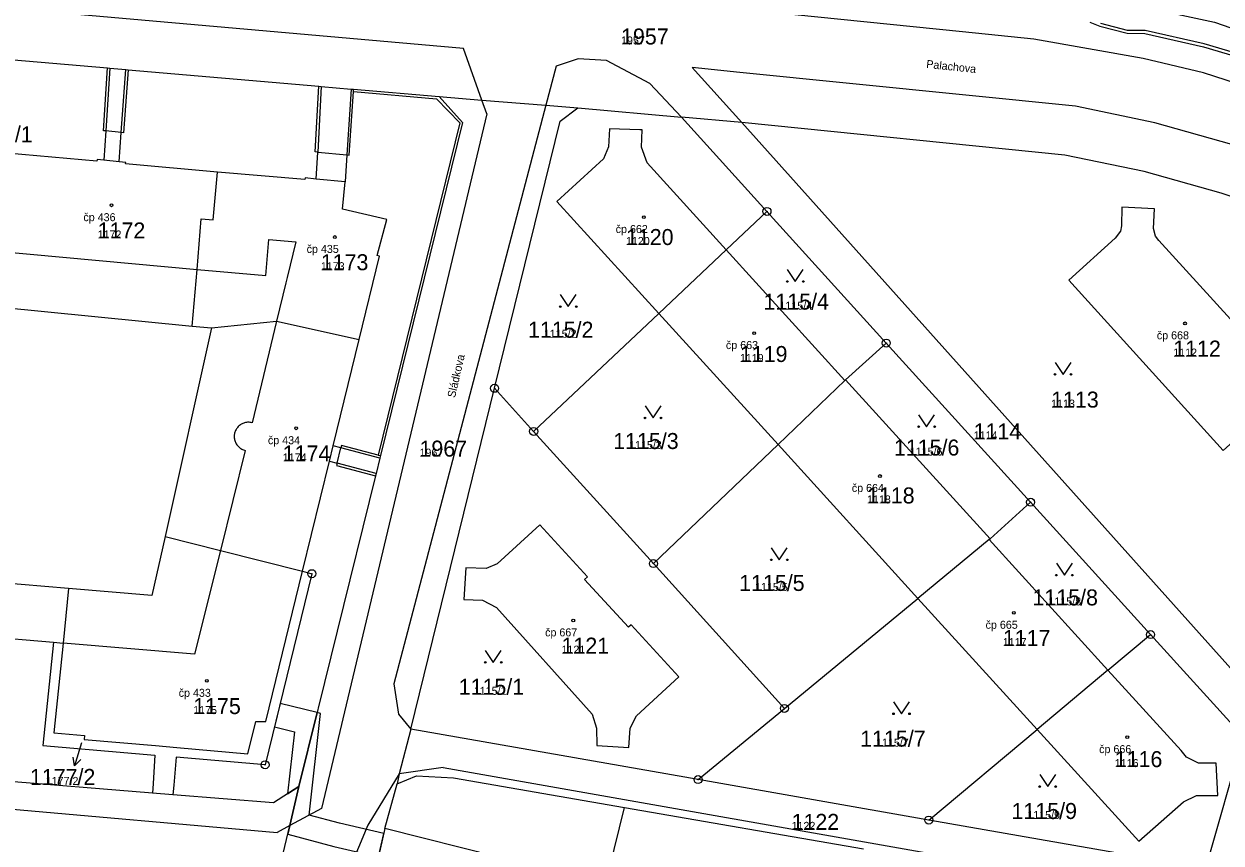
# Model space of a CAD drawing. Extents: x -763628 to -761565, y -976033 to -973833.
# Drawn here: x -762144.5 to -761994.9, y -975118.1 to -975015.7 of the extents above; entities that cross this region are included whole.
import ezdxf

# ---------------------------------------------------------------- set-up
doc = ezdxf.new("R2010")
doc.units = 0
for name, color, linetype in [('KN_cisla parcel 1000', 7, 'Continuous'), ('KN_cisla parcel 500', 7, 'Continuous'), ('KN_cisla parcel znacky', 7, 'Continuous'), ('KN_cisla popisna 500', 7, 'Continuous'), ('KN_hranice parcel', 7, 'Continuous'), ('KN_popisy', 7, 'Continuous'), ('KN_vecna bremena', 7, 'Continuous'), ('KN_vnitrni kresba parcel', 7, 'Continuous'), ('KN_znacky bodu BP', 7, 'Continuous'), ('KN_znacky budov', 7, 'Continuous'), ('KN_znacky kultur', 7, 'Continuous')]:
    doc.layers.add(name, color=color, linetype=linetype)

msp = doc.modelspace()

# ---------------------------------------------------------------- linework, layer by layer
at = {"layer": 'KN_cisla parcel znacky'}
for p, q in [((-762137.32, -975105.63), (-762138.2, -975108.5)), ((-762138.2, -975108.5), (-762138.38, -975107.4)), ((-762138.2, -975108.5), (-762137.43, -975107.69))]:
    msp.add_line(p, q, dxfattribs=at)
at = {"layer": 'KN_hranice parcel'}
for p, q in [((-762075.32, -975026.21), (-762062.36, -975027.36)), ((-762054.8, -975028.04), (-762062.36, -975027.36)), ((-762062.36, -975027.36), (-762051.67, -975039.16)), ((-762054.8, -975028.04), (-761990.72, -975099.69)), ((-762056.78, -975043.98), (-762051.67, -975039.16)), ((-762051.67, -975039.16), (-762036.76, -975055.62)), ((-762056.78, -975043.98), (-762065.19, -975051.92)), ((-762041.95, -975060.32), (-762056.78, -975043.98)), ((-762148.53, -975051.01), (-762123.49, -975053.49)), ((-762080.83, -975066.67), (-762065.19, -975051.92)), ((-762065.19, -975051.92), (-762050.29, -975068.31)), ((-762121.08, -975053.73), (-762126.89, -975079.8)), ((-762123.49, -975053.49), (-762121.08, -975053.73)), ((-762041.84, -975060.22), (-762036.76, -975055.62)), ((-762036.76, -975055.62), (-762018.73, -975075.52)), ((-762041.84, -975060.22), (-762041.95, -975060.32)), ((-762023.79, -975080.09), (-762041.84, -975060.22)), ((-762096.2, -975103.92), (-762085.72, -975061.28)), ((-762080.83, -975066.67), (-762085.72, -975061.28)), ((-762041.95, -975060.32), (-762050.29, -975068.31)), ((-762065.87, -975083.2), (-762080.83, -975066.67)), ((-762065.87, -975083.2), (-762050.29, -975068.31)), ((-762050.29, -975068.31), (-762032.81, -975087.55)), ((-762023.79, -975080.09), (-762018.73, -975075.52)), ((-762018.73, -975075.52), (-762003.73, -975092.08)), ((-762023.9, -975080.19), (-762032.81, -975087.55)), ((-762023.9, -975080.19), (-762023.79, -975080.09)), ((-762009.07, -975096.52), (-762023.9, -975080.19)), ((-762049.5, -975101.31), (-762065.87, -975083.2)), ((-762049.5, -975101.31), (-762032.81, -975087.55)), ((-762032.81, -975087.55), (-762017.92, -975103.94)), ((-762140.85, -975093.03), (-762139.65, -975093.13)), ((-762009.07, -975096.52), (-762003.73, -975092.08)), ((-762003.73, -975092.08), (-761992.18, -975104.83)), ((-762009.07, -975096.52), (-762017.92, -975103.94)), ((-762060.28, -975110.21), (-762049.5, -975101.31)), ((-762060.28, -975110.21), (-762096.2, -975103.92)), ((-762031.45, -975115.27), (-762017.92, -975103.94)), ((-761992.18, -975104.83), (-761996.86, -975121.33)), ((-762128.45, -975111.89), (-762150.74, -975110.1)), ((-762099.41, -975116.32), (-762097.9, -975110.76)), ((-762090.86, -975110.01), (-762069.47, -975113.71)), ((-762031.45, -975115.27), (-762060.28, -975110.21)), ((-762125.91, -975112.1), (-762128.45, -975111.89)), ((-762077.74, -975147.37), (-762069.47, -975113.71)), ((-762069.47, -975113.71), (-762039.6, -975118.87)), ((-761996.86, -975121.33), (-762031.45, -975115.27)), ((-762099.41, -975116.32), (-762101.69, -975126.28))]:
    msp.add_line(p, q, dxfattribs=at)
for points in [[(-762003.31, -975013.86), (-761995.75, -975015.5), (-761988.77, -975017.9), (-761988.34, -975018.04), (-761985.18, -975019.03)], [(-762197.02, -975015.78), (-762187.5, -975016.6), (-762187.21, -975016.63), (-762185.26, -975016.8), (-762184.97, -975016.82), (-762160.6, -975018.93), (-762160.3, -975018.95), (-762158.34, -975019.12), (-762158.04, -975019.15), (-762134.08, -975021.22), (-762133.78, -975021.24), (-762131.8, -975021.42), (-762131.5, -975021.44), (-762107.67, -975023.5), (-762107.37, -975023.53), (-762103.63, -975023.85), (-762103.34, -975023.88), (-762092.64, -975024.8)], [(-762092.64, -975024.8), (-762089.73, -975028.02), (-762099.99, -975069.7), (-762100.06, -975070), (-762100.53, -975071.92), (-762100.6, -975072.21), (-762110.16, -975111.06)], [(-762092.64, -975024.8), (-762087.3, -975025.23), (-762079.29, -975025.89), (-762075.32, -975026.21)], [(-762085.72, -975061.28), (-762077.5, -975027.86), (-762075.32, -975026.21)], [(-762056.78, -975043.98), (-762066.66, -975033.1), (-762067.35, -975031.14), (-762067.28, -975028.97), (-762067.58, -975028.96), (-762071.37, -975028.84), (-762071.49, -975031.07), (-762072.09, -975032.58), (-762077.93, -975037.9), (-762065.19, -975051.92)], [(-761977.51, -975044.15), (-761979.7, -975042.42), (-761987.36, -975039.43), (-761994.91, -975036.88), (-762004.52, -975034.15), (-762014.44, -975032.12), (-762054.8, -975028.04)], [(-762120.35, -975034.25), (-762131.83, -975033.22), (-762131.81, -975033.04), (-762132.64, -975032.95), (-762134.55, -975032.75), (-762135.4, -975032.66), (-762135.42, -975032.88), (-762146.69, -975031.88)], [(-762123.49, -975053.49), (-762122.9, -975046.4), (-762122.37, -975040.1), (-762120.87, -975040.23), (-762120.35, -975034.25)], [(-762102.64, -975055.16), (-762100.1, -975044.77), (-762100.39, -975044.69), (-762099.19, -975040.18), (-762104.7, -975038.89), (-762104.4, -975035.47), (-762108.01, -975035.11), (-762109.39, -975034.97), (-762109.41, -975035.16), (-762120.35, -975034.25)], [(-762007.38, -975040.97), (-762007.5, -975041.64), (-762008.16, -975042.49), (-762013.95, -975047.77), (-761994.66, -975069.04), (-761988.76, -975063.7), (-761987.08, -975063.17), (-761984.81, -975063.25), (-761984.64, -975059.18), (-761986.84, -975059.01), (-761988.64, -975058.26), (-762002.72, -975042.8), (-762003.11, -975042.25), (-762003.38, -975041.31), (-762003.26, -975038.84), (-762007.33, -975038.64), (-762007.38, -975040.97)], [(-762121.08, -975053.73), (-762112.96, -975052.9), (-762102.64, -975055.16)], [(-762109.72, -975084.16), (-762106.36, -975070.39), (-762105.89, -975068.48), (-762102.64, -975055.16)], [(-762068.99, -975091.16), (-762074.46, -975085.19), (-762074.1, -975084.86), (-762080.04, -975078.37), (-762085.39, -975083.22), (-762086.78, -975083.81), (-762089.32, -975083.74), (-762089.56, -975087.7), (-762087.22, -975087.78), (-762085.46, -975088.7), (-762073.51, -975102.02), (-762072.96, -975103.78), (-762072.93, -975105.96), (-762068.93, -975106.19), (-762068.78, -975103.76), (-762067.99, -975102.24), (-762062.67, -975097.37), (-762068.64, -975090.84), (-762068.99, -975091.16)], [(-762126.89, -975079.8), (-762128.53, -975087.18), (-762138.95, -975086.31), (-762139.65, -975093.13)], [(-762126.89, -975079.8), (-762119.98, -975081.55), (-762109.72, -975084.16)], [(-762139.65, -975093.13), (-762140.8, -975104.35), (-762136.95, -975104.7), (-762136.99, -975105.18), (-762128.08, -975105.96), (-762125.42, -975106.2), (-762116.57, -975106.97), (-762115.57, -975102.93), (-762114.3, -975102.93), (-762109.72, -975084.16)], [(-762109.72, -975084.16), (-762108.56, -975084.46), (-762114.39, -975108.36), (-762125.52, -975107.4), (-762125.81, -975110.9), (-762125.91, -975112.1)], [(-762150.74, -975110.1), (-762154.66, -975108.46), (-762156.03, -975105.41), (-762155.42, -975097.52), (-762153.33, -975094.1), (-762149.67, -975092.29), (-762140.85, -975093.03)], [(-762140.85, -975093.03), (-762142.17, -975105.93), (-762128.16, -975107.16), (-762128.38, -975110.69), (-762128.45, -975111.89)], [(-762017.92, -975103.94), (-762005.2, -975117.93), (-761999.6, -975113.01), (-761997.99, -975112.21), (-761995.31, -975112.22), (-761995.52, -975108.16), (-761997.73, -975108.16), (-761999.24, -975107.39), (-761999.93, -975106.59), (-762009.07, -975096.52)], [(-762096.2, -975103.92), (-762097.63, -975109.51), (-762097.9, -975110.76)], [(-762110.16, -975111.06), (-762113.34, -975113.11), (-762125.91, -975112.1)], [(-762113.48, -975125.21), (-762112.7, -975121.9), (-762111.31, -975115.95), (-762110.16, -975111.06)], [(-762097.9, -975110.76), (-762095.49, -975109.76), (-762090.86, -975110.01)], [(-762087.88, -975144.88), (-762084.3, -975130.34), (-762087.6, -975129.52), (-762085.23, -975119.93), (-762099.41, -975116.32)]]:
    msp.add_lwpolyline(points, dxfattribs=at)
at = {"layer": 'KN_vecna bremena'}
for points in [[(-762011.34, -975015.47), (-762010.07, -975016.01), (-762006.64, -975016.86), (-762004.44, -975016.89), (-761997.13, -975018.56), (-761989.39, -975020.85)], [(-761989.29, -975020.51), (-761997.05, -975018.22), (-762004.4, -975016.55), (-762006.6, -975016.52), (-762009.95, -975015.67)]]:
    msp.add_lwpolyline(points, dxfattribs=at)
for points in [[(-762112.52, -975100.71), (-762113.23, -975103.62), (-762110.73, -975104.23), (-762111.6, -975111.99), (-762110.16, -975111.06), (-762107.89, -975101.84)], [(-762107.89, -975101.84), (-762110.16, -975111.06), (-762111.31, -975115.95), (-762111.56, -975117.03), (-762105.82, -975118.56), (-762100.23, -975119.89), (-762099.56, -975116.96), (-762105.09, -975115.65), (-762108.87, -975114.64), (-762107.45, -975101.95)]]:
    msp.add_lwpolyline(points, close=True, dxfattribs=at)
at = {"layer": 'KN_vnitrni kresba parcel'}
for p, q in [((-762089.61, -975018.78), (-762197.77, -975009.24)), ((-762027.23, -975016.7), (-762070.01, -975012.34)), ((-762018.31, -975017.63), (-762027.23, -975016.7)), ((-762004.64, -975020.02), (-762018.31, -975017.63)), ((-762087.3, -975025.23), (-762089.61, -975018.78)), ((-762134.6, -975029.07), (-762134.08, -975021.22)), ((-762133.78, -975021.24), (-762134.3, -975029.09)), ((-762078, -975021), (-762079.29, -975025.89)), ((-762075.26, -975020.08), (-762078, -975021)), ((-762071.72, -975020.3), (-762075.26, -975020.08)), ((-762066.3, -975023.14), (-762071.72, -975020.3)), ((-762061.03, -975021.17), (-762054.8, -975028.04)), ((-762055.06, -975021.77), (-762061.03, -975021.17)), ((-761997.12, -975021.83), (-762004.64, -975020.02)), ((-762132.37, -975029.29), (-762131.8, -975021.42)), ((-762131.5, -975021.44), (-762132.07, -975029.31)), ((-762013.12, -975026), (-762055.06, -975021.77)), ((-761982.88, -975026.4), (-761997.12, -975021.83)), ((-762108.12, -975031.71), (-762107.67, -975023.5)), ((-762107.37, -975023.53), (-762107.82, -975031.73)), ((-762103.63, -975023.85), (-762104.18, -975032.09)), ((-762103.88, -975032.11), (-762103.35, -975024.17)), ((-762103.35, -975024.17), (-762103.34, -975023.88)), ((-762103.35, -975024.17), (-762092.97, -975025.07)), ((-762062.36, -975027.36), (-762066.3, -975023.14)), ((-762092.97, -975025.07), (-762090.06, -975028.09)), ((-762086.69, -975026.94), (-762087.3, -975025.23)), ((-762086.69, -975026.94), (-762107.35, -975113.81)), ((-762079.29, -975025.89), (-762098.32, -975098.23)), ((-762003.2, -975028.07), (-762013.12, -975026)), ((-762090.06, -975028.09), (-762100.28, -975069.62)), ((-761993.59, -975030.77), (-762003.2, -975028.07)), ((-762134.3, -975029.09), (-762134.6, -975029.07)), ((-762134.3, -975029.09), (-762134.55, -975032.75)), ((-762132.37, -975029.29), (-762134.3, -975029.09)), ((-762132.64, -975032.95), (-762132.37, -975029.29)), ((-762132.07, -975029.31), (-762132.37, -975029.29)), ((-762107.82, -975031.73), (-762108.12, -975031.71)), ((-762108.01, -975035.11), (-762107.82, -975031.73)), ((-762107.82, -975031.73), (-762104.18, -975032.09)), ((-762104.18, -975032.09), (-762104.4, -975035.47)), ((-762104.18, -975032.09), (-762103.88, -975032.11)), ((-762114.32, -975047.18), (-762113.91, -975042.68)), ((-762113.91, -975042.68), (-762110.57, -975042.96)), ((-762110.57, -975042.96), (-762111.65, -975047.42)), ((-762147.87, -975044.13), (-762122.9, -975046.4)), ((-762122.9, -975046.4), (-762114.32, -975047.18)), ((-762111.81, -975048.1), (-762112.96, -975052.9)), ((-762111.65, -975047.42), (-762111.81, -975048.1)), ((-762112.96, -975052.9), (-762116.02, -975065.59)), ((-762116.87, -975069.04), (-762119.98, -975081.55)), ((-762104.92, -975068.73), (-762105.89, -975068.48)), ((-762105.39, -975070.63), (-762104.92, -975068.73)), ((-762104.85, -975068.44), (-762104.92, -975068.73)), ((-762100.06, -975070), (-762104.92, -975068.73)), ((-762100.28, -975069.62), (-762104.85, -975068.44)), ((-762106.36, -975070.39), (-762105.39, -975070.63)), ((-762105.39, -975070.63), (-762105.46, -975070.92)), ((-762100.53, -975071.92), (-762105.39, -975070.63)), ((-762100.28, -975069.62), (-762099.99, -975069.7)), ((-762105.46, -975070.92), (-762100.6, -975072.21)), ((-762119.98, -975081.55), (-762123.22, -975094.54)), ((-762138.95, -975086.31), (-762174.14, -975083.36)), ((-762123.22, -975094.54), (-762139.65, -975093.13)), ((-762098.32, -975098.23), (-762097.73, -975102.02)), ((-762097.73, -975102.02), (-762096.2, -975103.92)), ((-762206.5, -975108.64), (-762112.89, -975116.81)), ((-762097.63, -975109.51), (-762101.57, -975115.89)), ((-762092.15, -975108.68), (-762097.63, -975109.51)), ((-762092.15, -975108.68), (-762005.33, -975124)), ((-762107.35, -975113.81), (-762111.31, -975115.95)), ((-762111.31, -975115.95), (-762112.89, -975116.81)), ((-762101.57, -975115.89), (-762104.35, -975122.6))]:
    msp.add_line(p, q, dxfattribs=at)
msp.add_lwpolyline([(-762116.02, -975065.59), (-762116.14, -975065.56), (-762116.25, -975065.55), (-762116.37, -975065.53), (-762116.49, -975065.53), (-762116.6, -975065.53), (-762116.72, -975065.55), (-762116.84, -975065.57), (-762116.95, -975065.59), (-762117.06, -975065.63), (-762117.17, -975065.67), (-762117.28, -975065.72), (-762117.38, -975065.78), (-762117.48, -975065.84), (-762117.58, -975065.91), (-762117.67, -975065.99), (-762117.75, -975066.07), (-762117.83, -975066.16), (-762117.9, -975066.25), (-762117.97, -975066.34), (-762118.03, -975066.45), (-762118.09, -975066.55), (-762118.13, -975066.66), (-762118.17, -975066.77), (-762118.2, -975066.88), (-762118.23, -975067), (-762118.24, -975067.11), (-762118.25, -975067.23), (-762118.25, -975067.35), (-762118.25, -975067.47), (-762118.23, -975067.58), (-762118.21, -975067.7), (-762118.18, -975067.81), (-762118.14, -975067.92), (-762118.1, -975068.03), (-762118.05, -975068.14), (-762117.99, -975068.24), (-762117.93, -975068.34), (-762117.85, -975068.43), (-762117.78, -975068.52), (-762117.69, -975068.6), (-762117.6, -975068.68), (-762117.51, -975068.75), (-762117.41, -975068.82), (-762117.31, -975068.88), (-762117.2, -975068.93), (-762117.1, -975068.97), (-762116.98, -975069.01), (-762116.87, -975069.04)], dxfattribs=at)
at = {"layer": 'KN_znacky bodu BP'}
for centre, radius in [((-762051.67, -975039.16), 0.5), ((-762051.67, -975039.16), 0.0303), ((-762036.76, -975055.62), 0.5), ((-762036.76, -975055.62), 0.0303), ((-762085.72, -975061.28), 0.5), ((-762085.72, -975061.28), 0.0303), ((-762080.83, -975066.67), 0.5), ((-762080.83, -975066.67), 0.0303), ((-762018.73, -975075.52), 0.5), ((-762018.73, -975075.52), 0.0303), ((-762065.87, -975083.2), 0.5), ((-762108.56, -975084.46), 0.5), ((-762065.87, -975083.2), 0.0303), ((-762108.56, -975084.46), 0.0303), ((-762003.73, -975092.08), 0.5), ((-762003.73, -975092.08), 0.0303), ((-762049.5, -975101.31), 0.5), ((-762049.5, -975101.31), 0.0303), ((-762114.39, -975108.36), 0.5), ((-762114.39, -975108.36), 0.0303), ((-762060.28, -975110.21), 0.5), ((-762060.28, -975110.21), 0.0303), ((-762031.45, -975115.27), 0.5), ((-762031.45, -975115.27), 0.0303)]:
    msp.add_circle(centre, radius, dxfattribs=at)
at = {"layer": 'KN_znacky budov'}
for centre in [(-762133.58, -975038.39), (-762067.06, -975039.87), (-762105.68, -975042.36), (-762053.28, -975054.38), (-761999.43, -975053.16), (-762110.52, -975066.28), (-762037.55, -975072.25), (-762075.88, -975090.31), (-762020.83, -975089.36), (-762121.67, -975097.87), (-762006.64, -975104.91)]:
    msp.add_circle(centre, 0.175, dxfattribs=at)
at = {"layer": 'KN_znacky kultur'}
for points in [[(-762049.13, -975046.42), (-762048.13, -975047.92), (-762047.13, -975046.42)], [(-762077.5, -975049.56), (-762076.5, -975051.06), (-762075.5, -975049.56)], [(-762015.67, -975058.04), (-762014.67, -975059.54), (-762013.67, -975058.04)], [(-762066.91, -975063.48), (-762065.91, -975064.98), (-762064.91, -975063.48)], [(-762032.72, -975064.58), (-762031.72, -975066.08), (-762030.72, -975064.58)], [(-762051.13, -975081.23), (-762050.13, -975082.73), (-762049.13, -975081.23)], [(-762015.5, -975083.15), (-762014.5, -975084.65), (-762013.5, -975083.15)], [(-762086.88, -975094.05), (-762085.88, -975095.55), (-762084.88, -975094.05)], [(-762035.86, -975100.48), (-762034.86, -975101.98), (-762033.86, -975100.48)], [(-762017.59, -975109.58), (-762016.59, -975111.08), (-762015.59, -975109.58)]]:
    msp.add_lwpolyline(points, dxfattribs=at)
for centre in [(-762049.13, -975047.92), (-762047.13, -975047.92), (-762077.5, -975051.06), (-762075.5, -975051.06), (-762015.67, -975059.54), (-762013.67, -975059.54), (-762066.91, -975064.98), (-762064.91, -975064.98), (-762032.72, -975066.08), (-762030.72, -975066.08), (-762051.13, -975082.73), (-762049.13, -975082.73), (-762015.5, -975084.65), (-762013.5, -975084.65), (-762086.88, -975095.55), (-762084.88, -975095.55), (-762035.86, -975101.98), (-762033.86, -975101.98), (-762017.59, -975111.08), (-762015.59, -975111.08)]:
    msp.add_circle(centre, 0.1, dxfattribs=at)

# ---------------------------------------------------------------- texts
at = {"layer": 'KN_cisla parcel 1000'}
for s, p in [('1957', (-762069.91, -975018.28)), ('1177/1', (-762151.62, -975030.51)), ('1172', (-762135.32, -975042.54)), ('1120', (-762069.3, -975043.36)), ('1173', (-762107.43, -975046.51)), ('1115/4', (-762052.11, -975051.44)), ('1115/2', (-762081.54, -975054.95)), ('1112', (-762000.9, -975057.31)), ('1119', (-762055.06, -975057.99)), ('1113', (-762016.16, -975063.69)), ('1114', (-762025.85, -975067.67)), ('1115/3', (-762070.89, -975068.87)), ('1115/6', (-762035.81, -975069.69)), ('1174', (-762112.19, -975070.43)), ('1967', (-762095.1, -975069.82)), ('1118', (-762039.17, -975075.68)), ('1115/5', (-762055.15, -975086.62)), ('1115/8', (-762018.49, -975088.43)), ('1117', (-762022.2, -975093.51)), ('1121', (-762077.35, -975094.46)), ('1115/1', (-762090.2, -975099.61)), ('1175', (-762123.38, -975102.02)), ('1115/7', (-762040.03, -975106.09)), ('1116', (-762008.21, -975108.65)), ('1177/2', (-762143.79, -975110.88)), ('1115/9', (-762021.11, -975115.14)), ('1122', (-762048.6, -975116.5))]:
    msp.add_text(s, height=2, dxfattribs=at).set_placement(p)
at = {"layer": 'KN_cisla parcel 500'}
for s, p in [('1957', (-762069.91, -975018.28)), ('1172', (-762135.32, -975042.54)), ('1120', (-762069.3, -975043.36)), ('1173', (-762107.43, -975046.51)), ('1115/4', (-762050.11, -975051.44)), ('1115/2', (-762079.56, -975054.95)), ('1119', (-762055.06, -975057.99)), ('1112', (-762000.9, -975057.31)), ('1113', (-762016.16, -975063.69)), ('1114', (-762025.85, -975067.67)), ('1967', (-762095.1, -975069.82)), ('1115/3', (-762068.91, -975068.87)), ('1115/6', (-762033.83, -975069.69)), ('1174', (-762112.19, -975070.43)), ('1118', (-762039.17, -975075.68)), ('1115/5', (-762053.17, -975086.62)), ('1115/8', (-762016.5, -975088.43)), ('1117', (-762022.2, -975093.51)), ('1121', (-762077.35, -975094.46)), ('1115/1', (-762088.31, -975099.61)), ('1175', (-762123.38, -975102.02)), ('1115/7', (-762038.05, -975106.09)), ('1116', (-762008.21, -975108.65)), ('1177/2', (-762141.81, -975110.88)), ('1115/9', (-762019.14, -975115.14)), ('1122', (-762048.6, -975116.5))]:
    msp.add_text(s, height=1, dxfattribs=at).set_placement(p)
at = {"layer": 'KN_cisla popisna 500'}
for s, p in [('čp 436', (-762137.1, -975040.38)), ('čp 662', (-762070.58, -975041.86)), ('čp 435', (-762109.2, -975044.35)), ('čp 668', (-762002.95, -975055.15)), ('čp 663', (-762056.8, -975056.37)), ('čp 434', (-762114.04, -975068.27)), ('čp 664', (-762041.07, -975074.24)), ('čp 667', (-762079.4, -975092.3)), ('čp 665', (-762024.35, -975091.35)), ('čp 433', (-762125.19, -975099.86)), ('čp 666', (-762010.16, -975106.9))]:
    msp.add_text(s, height=1, dxfattribs=at).set_placement(p)
at = {"layer": 'KN_popisy'}
for s, rotation, p in [('Palachova', 354, (-762031.8, -975021.2)), ('Sládkova', 77, (-762090.66, -975062.52))]:
    msp.add_text(s, height=1, rotation=rotation, dxfattribs=at).set_placement(p)

doc.saveas('drawing.dxf')
